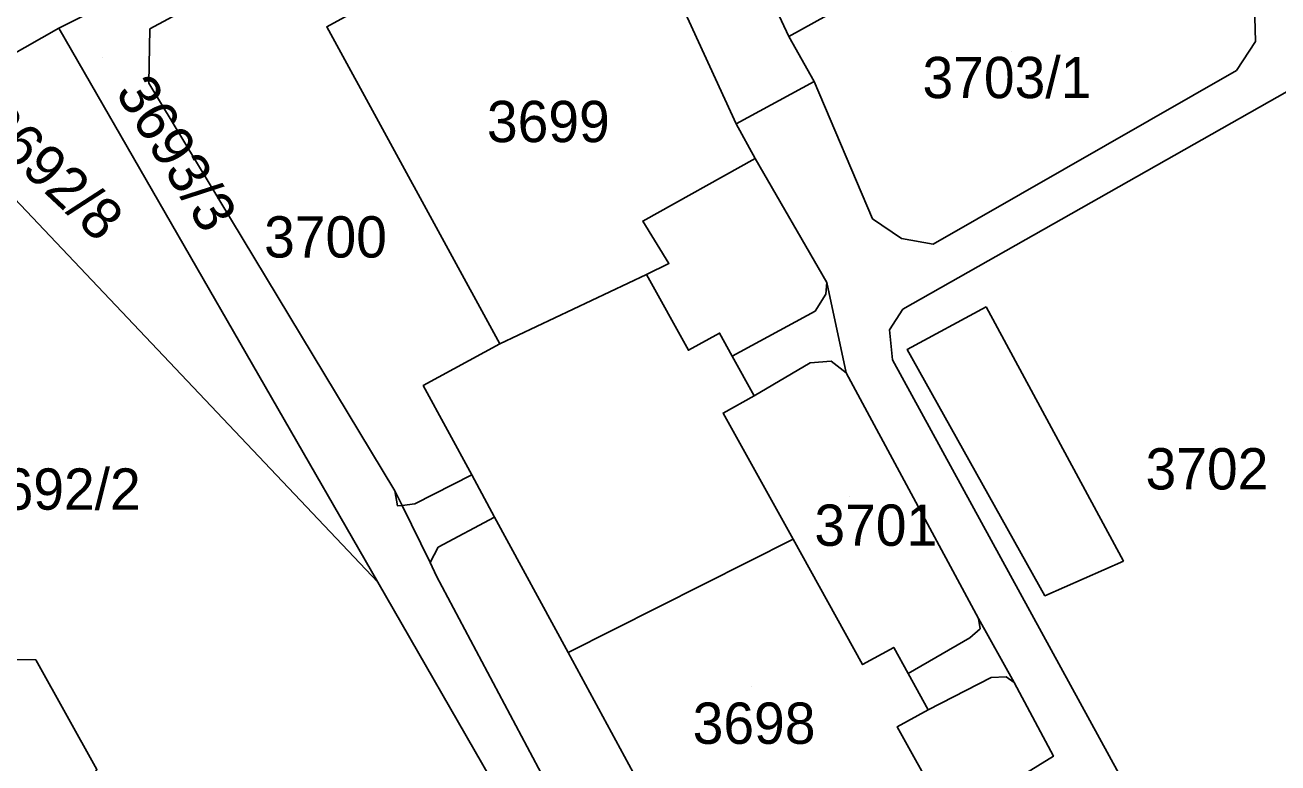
# Model space of a CAD drawing. Extents: x -262715 to -259381, y -1237238 to -1231182.
# Drawn here: x -261788.7 to -261728, y -1235674.8 to -1235639 of the extents above; entities that cross this region are included whole.
import ezdxf

# ---------------------------------------------------------------- set-up
doc = ezdxf.new("R2010")
doc.units = 0
for name, color, linetype in [('body_kn', 7, 'Continuous'), ('kladpar_druhypozemkov', 7, 'Continuous'), ('kladpar_hranice', 7, 'Continuous'), ('kladpar_parcelnecisla', 7, 'Continuous'), ('kladpar_plochy', 7, 'Continuous'), ('zappar_hrandruhpozemk', 7, 'Continuous')]:
    doc.layers.add(name, color=color, linetype=linetype)

msp = doc.modelspace()

# ---------------------------------------------------------------- linework, layer by layer
at = {"layer": 'body_kn'}
for p, q in [((-261787.06, -1235639.18), (-261787.06, -1235639.18)), ((-261787.06, -1235639.18), (-261787.06, -1235639.18)), ((-261782.66, -1235639.22), (-261782.66, -1235639.22)), ((-261774.08, -1235639.11), (-261774.08, -1235639.11)), ((-261751.7, -1235639.59), (-261751.7, -1235639.59)), ((-261729.08, -1235639.83), (-261729.08, -1235639.83)), ((-261730, -1235641.23), (-261730, -1235641.23)), ((-261782.71, -1235641.84), (-261782.71, -1235641.84)), ((-261750.47, -1235641.76), (-261750.47, -1235641.76)), ((-261754.24, -1235643.82), (-261754.24, -1235643.82)), ((-261753.32, -1235645.49), (-261753.32, -1235645.49)), ((-261753.32, -1235645.49), (-261753.32, -1235645.49)), ((-261758.77, -1235648.52), (-261758.77, -1235648.52)), ((-261747.64, -1235648.41), (-261747.64, -1235648.41)), ((-261746.24, -1235649.37), (-261746.24, -1235649.37)), ((-261744.7, -1235649.64), (-261744.7, -1235649.64)), ((-261757.51, -1235650.57), (-261757.51, -1235650.57)), ((-261758.6, -1235651.11), (-261758.6, -1235651.11)), ((-261758.6, -1235651.11), (-261758.6, -1235651.11)), ((-261749.85, -1235651.5), (-261749.85, -1235651.5)), ((-261749.85, -1235651.5), (-261749.85, -1235651.5)), ((-261749.91, -1235652.06), (-261749.91, -1235652.06)), ((-261750.42, -1235652.89), (-261750.42, -1235652.89)), ((-261746.17, -1235652.79), (-261746.17, -1235652.79)), ((-261742.14, -1235652.68), (-261742.14, -1235652.68)), ((-261742.14, -1235652.68), (-261742.14, -1235652.68)), ((-261755.05, -1235653.95), (-261755.05, -1235653.95)), ((-261746.82, -1235653.79), (-261746.82, -1235653.79)), ((-261765.69, -1235654.47), (-261765.69, -1235654.47)), ((-261756.56, -1235654.78), (-261756.56, -1235654.78)), ((-261754.44, -1235655.06), (-261754.44, -1235655.06)), ((-261749.65, -1235655.3), (-261749.65, -1235655.3)), ((-261746.67, -1235655.25), (-261746.67, -1235655.25)), ((-261745.96, -1235654.74), (-261745.96, -1235654.74)), ((-261750.67, -1235655.39), (-261750.67, -1235655.39)), ((-261748.92, -1235655.88), (-261748.92, -1235655.88)), ((-261769.41, -1235656.49), (-261769.41, -1235656.49)), ((-261753.37, -1235656.99), (-261753.37, -1235656.99)), ((-261753.37, -1235656.99), (-261753.37, -1235656.99)), ((-261754.88, -1235657.82), (-261754.88, -1235657.82)), ((-261767.05, -1235660.82), (-261767.05, -1235660.82)), ((-261767.05, -1235660.82), (-261767.05, -1235660.82)), ((-261770.78, -1235661.58), (-261770.78, -1235661.58)), ((-261770.65, -1235662.32), (-261770.65, -1235662.32)), ((-261770.43, -1235662.29), (-261770.43, -1235662.29)), ((-261770.43, -1235662.29), (-261770.43, -1235662.29)), ((-261769.81, -1235662.22), (-261769.81, -1235662.22)), ((-261765.95, -1235662.86), (-261765.95, -1235662.86)), ((-261765.95, -1235662.86), (-261765.95, -1235662.86)), ((-261768.68, -1235664.32), (-261768.68, -1235664.32)), ((-261751.49, -1235663.92), (-261751.49, -1235663.92)), ((-261751.49, -1235663.92), (-261751.49, -1235663.92)), ((-261735.48, -1235665), (-261735.48, -1235665)), ((-261769.08, -1235665.05), (-261769.08, -1235665.05)), ((-261771.61, -1235666.01), (-261771.61, -1235666.01)), ((-261771.61, -1235666.01), (-261771.61, -1235666.01)), ((-261768.76, -1235665.72), (-261768.76, -1235665.72)), ((-261739.29, -1235666.67), (-261739.29, -1235666.67)), ((-261742.51, -1235667.77), (-261742.51, -1235667.77)), ((-261742.51, -1235667.77), (-261742.51, -1235667.77)), ((-261742.42, -1235668.27), (-261742.42, -1235668.27)), ((-261746.61, -1235669.17), (-261746.61, -1235669.17)), ((-261742.93, -1235668.7), (-261742.93, -1235668.7)), ((-261788.18, -1235669.77), (-261788.18, -1235669.77)), ((-261762.39, -1235669.41), (-261762.39, -1235669.41)), ((-261748.12, -1235670), (-261748.12, -1235670)), ((-261745.91, -1235670.44), (-261745.91, -1235670.44)), ((-261741.9, -1235670.62), (-261741.9, -1235670.62)), ((-261741.17, -1235670.59), (-261741.17, -1235670.59)), ((-261740.78, -1235670.87), (-261740.78, -1235670.87)), ((-261744.94, -1235672.19), (-261744.94, -1235672.19)), ((-261744.94, -1235672.19), (-261744.94, -1235672.19)), ((-261746.45, -1235673.02), (-261746.45, -1235673.02)), ((-261738.88, -1235674.44), (-261738.88, -1235674.44))]:
    msp.add_line(p, q, dxfattribs=at)
at = {"layer": 'kladpar_druhypozemkov'}
for p, q in [((-261784.94, -1235640.58), (-261784.94, -1235640.58)), ((-261740.91, -1235640.29), (-261740.91, -1235640.29)), ((-261763.21, -1235642.76), (-261763.21, -1235642.76)), ((-261786.49, -1235645.69), (-261786.49, -1235645.69)), ((-261774.4, -1235648.58), (-261774.4, -1235648.58)), ((-261731.03, -1235659.45), (-261731.03, -1235659.45)), ((-261786.19, -1235660.91), (-261786.19, -1235660.91)), ((-261748.77, -1235661.87), (-261748.77, -1235661.87)), ((-261753.52, -1235671.05), (-261753.52, -1235671.05))]:
    msp.add_line(p, q, dxfattribs=at)
at = {"layer": 'kladpar_hranice'}
for points in [[(-261746.87, -1235614.31), (-261744.89, -1235617.96), (-261743.11, -1235621.2), (-261744.08, -1235621.73), (-261743.02, -1235623.67), (-261740.4, -1235622.23), (-261735.74, -1235630.75), (-261751.7, -1235639.59), (-261755.64, -1235631.15), (-261753.61, -1235629.87), (-261756.52, -1235624.52), (-261755.14, -1235623.41), (-261755.48, -1235622.77), (-261756.99, -1235619.94), (-261746.87, -1235614.31)], [(-261741.48, -1235615.82), (-261739.49, -1235619.29), (-261738.43, -1235621.27), (-261729.14, -1235638.06), (-261729.08, -1235639.83), (-261730, -1235641.23), (-261744.7, -1235649.64), (-261746.24, -1235649.37), (-261747.64, -1235648.41), (-261750.47, -1235641.76), (-261751.7, -1235639.59), (-261735.74, -1235630.75), (-261740.4, -1235622.23), (-261743.02, -1235623.67), (-261744.08, -1235621.73), (-261743.11, -1235621.2), (-261744.89, -1235617.96), (-261741.48, -1235615.82)], [(-261787.06, -1235639.18), (-261782.81, -1235637.04), (-261775.1, -1235633.15), (-261772.73, -1235630.76), (-261772.47, -1235630.53)], [(-261755.64, -1235631.15), (-261751.7, -1235639.59), (-261750.47, -1235641.76), (-261754.24, -1235643.82), (-261753.32, -1235645.49), (-261758.77, -1235648.52), (-261757.51, -1235650.57), (-261758.6, -1235651.11), (-261765.69, -1235654.47), (-261774.08, -1235639.11), (-261765.58, -1235634.46), (-261764.15, -1235636.92), (-261762.21, -1235635.85), (-261762.74, -1235634.88), (-261759.23, -1235632.96), (-261755.64, -1235631.15)], [(-261793.56, -1235642.86), (-261798.21, -1235637.96), (-261797.99, -1235637.92), (-261787.61, -1235632), (-261782.81, -1235637.04), (-261787.06, -1235639.18), (-261793.56, -1235642.86)], [(-261762.72, -1235677.09), (-261768.76, -1235665.72), (-261769.08, -1235665.05), (-261770.43, -1235662.29), (-261770.78, -1235661.58), (-261782.71, -1235641.84), (-261782.66, -1235639.22), (-261770.45, -1235632.64)], [(-261770.45, -1235632.64), (-261782.66, -1235639.22), (-261782.71, -1235641.84), (-261770.78, -1235661.58), (-261770.43, -1235662.29), (-261769.08, -1235665.05), (-261768.76, -1235665.72), (-261762.72, -1235677.09)], [(-261765.58, -1235634.46), (-261774.08, -1235639.11), (-261765.69, -1235654.47), (-261769.41, -1235656.49), (-261767.05, -1235660.82), (-261765.95, -1235662.86), (-261762.39, -1235669.41), (-261758.82, -1235676)], [(-261726.07, -1235688.93), (-261728.83, -1235696.49), (-261728.34, -1235694.86), (-261728.71, -1235693), (-261733.78, -1235683.75), (-261735.92, -1235679.87), (-261737.19, -1235677.55), (-261742.41, -1235680.43), (-261743.98, -1235677.59), (-261738.88, -1235674.44), (-261740.78, -1235670.87), (-261742.51, -1235667.77), (-261748.92, -1235655.88), (-261749.85, -1235651.5), (-261753.32, -1235645.49), (-261754.24, -1235643.82), (-261750.47, -1235641.76), (-261747.64, -1235648.41), (-261746.24, -1235649.37), (-261744.7, -1235649.64), (-261730, -1235641.23), (-261729.08, -1235639.83), (-261729.14, -1235638.06)], [(-261771.61, -1235666.01), (-261793.56, -1235642.86), (-261787.06, -1235639.18), (-261771.61, -1235666.01)], [(-261765.78, -1235676.15), (-261771.61, -1235666.01), (-261787.06, -1235639.18)], [(-261721.34, -1235645.46), (-261721.45, -1235663.19), (-261721.77, -1235676.13), (-261721.89, -1235682.46), (-261724.87, -1235687.88), (-261726.07, -1235688.93), (-261727.44, -1235689.02), (-261728.49, -1235688.46), (-261746.67, -1235655.25), (-261746.82, -1235653.79), (-261746.17, -1235652.79), (-261725.73, -1235641.21), (-261724.22, -1235640.89), (-261722.8, -1235641.31), (-261721.25, -1235642.86), (-261721.34, -1235645.46)], [(-261725.73, -1235641.21), (-261746.17, -1235652.79), (-261746.82, -1235653.79), (-261746.67, -1235655.25), (-261728.49, -1235688.46), (-261727.44, -1235689.02)], [(-261793.56, -1235642.86), (-261771.61, -1235666.01), (-261765.78, -1235676.15), (-261780.48, -1235684.16), (-261783.34, -1235684.15), (-261785.63, -1235682.73), (-261786.89, -1235680.9), (-261786.92, -1235678.28), (-261785.22, -1235675.09), (-261788.18, -1235669.77), (-261790.97, -1235669.73), (-261793.34, -1235668.35), (-261794.56, -1235666.02), (-261794.55, -1235663.58), (-261792.74, -1235660.97), (-261795.77, -1235655.64), (-261797.7, -1235656.01), (-261800, -1235655.29), (-261801.67, -1235653.66), (-261802.55, -1235651.24), (-261802.11, -1235648.87), (-261800.44, -1235646.76), (-261793.56, -1235642.86)], [(-261753.32, -1235645.49), (-261749.85, -1235651.5), (-261748.92, -1235655.88), (-261742.51, -1235667.77), (-261740.78, -1235670.87), (-261738.88, -1235674.44), (-261743.98, -1235677.59), (-261744.45, -1235676.62), (-261746.45, -1235673.02), (-261744.94, -1235672.19), (-261745.91, -1235670.44), (-261746.61, -1235669.17), (-261748.12, -1235670), (-261751.49, -1235663.92), (-261754.88, -1235657.82), (-261753.37, -1235656.99), (-261754.44, -1235655.06), (-261755.05, -1235653.95), (-261756.56, -1235654.78), (-261758.6, -1235651.11), (-261757.51, -1235650.57), (-261758.77, -1235648.52), (-261753.32, -1235645.49)], [(-261790.97, -1235669.73), (-261788.18, -1235669.77), (-261785.22, -1235675.09), (-261786.92, -1235678.28), (-261786.89, -1235680.9), (-261785.63, -1235682.73), (-261783.34, -1235684.15), (-261780.48, -1235684.16), (-261765.78, -1235676.15), (-261761.54, -1235683.52), (-261785.68, -1235696.18), (-261809.78, -1235651.59)], [(-261758.6, -1235651.11), (-261756.56, -1235654.78), (-261755.05, -1235653.95), (-261754.44, -1235655.06), (-261753.37, -1235656.99), (-261754.88, -1235657.82), (-261751.49, -1235663.92), (-261748.12, -1235670), (-261746.61, -1235669.17), (-261745.91, -1235670.44), (-261744.94, -1235672.19), (-261746.45, -1235673.02), (-261744.45, -1235676.62), (-261754.91, -1235682.08), (-261755.38, -1235682.34), (-261757.72, -1235678.03), (-261758.82, -1235676), (-261762.39, -1235669.41), (-261765.95, -1235662.86), (-261767.05, -1235660.82), (-261769.41, -1235656.49), (-261765.69, -1235654.47), (-261758.6, -1235651.11)]]:
    msp.add_lwpolyline(points, dxfattribs=at)
at = {"layer": 'kladpar_plochy'}
for points in [[(-261746.87, -1235614.31), (-261744.89, -1235617.96), (-261743.11, -1235621.2), (-261744.08, -1235621.73), (-261743.02, -1235623.67), (-261740.4, -1235622.23), (-261735.74, -1235630.75), (-261751.7, -1235639.59), (-261755.64, -1235631.15), (-261753.61, -1235629.87), (-261756.52, -1235624.52), (-261755.14, -1235623.41), (-261755.48, -1235622.77), (-261756.99, -1235619.94)], [(-261741.48, -1235615.82), (-261739.49, -1235619.29), (-261738.43, -1235621.27), (-261729.14, -1235638.06), (-261729.08, -1235639.83), (-261730, -1235641.23), (-261744.7, -1235649.64), (-261746.24, -1235649.37), (-261747.64, -1235648.41), (-261750.47, -1235641.76), (-261751.7, -1235639.59), (-261735.74, -1235630.75), (-261740.4, -1235622.23), (-261743.02, -1235623.67), (-261744.08, -1235621.73), (-261743.11, -1235621.2), (-261744.89, -1235617.96)], [(-261755.64, -1235631.15), (-261751.7, -1235639.59), (-261750.47, -1235641.76), (-261754.24, -1235643.82), (-261753.32, -1235645.49), (-261758.77, -1235648.52), (-261757.51, -1235650.57), (-261758.6, -1235651.11), (-261765.69, -1235654.47), (-261774.08, -1235639.11), (-261765.58, -1235634.46), (-261764.15, -1235636.92), (-261762.21, -1235635.85), (-261762.74, -1235634.88), (-261759.23, -1235632.96)], [(-261793.56, -1235642.86), (-261798.21, -1235637.96), (-261797.99, -1235637.92), (-261787.61, -1235632), (-261782.81, -1235637.04), (-261787.06, -1235639.18)], [(-261771.61, -1235666.01), (-261793.56, -1235642.86), (-261787.06, -1235639.18)], [(-261721.34, -1235645.46), (-261721.45, -1235663.19), (-261721.77, -1235676.13), (-261721.89, -1235682.46), (-261724.87, -1235687.88), (-261726.07, -1235688.93), (-261727.44, -1235689.02), (-261728.49, -1235688.46), (-261746.67, -1235655.25), (-261746.82, -1235653.79), (-261746.17, -1235652.79), (-261725.73, -1235641.21), (-261724.22, -1235640.89), (-261722.8, -1235641.31), (-261721.25, -1235642.86)], [(-261793.56, -1235642.86), (-261771.61, -1235666.01), (-261765.78, -1235676.15), (-261780.48, -1235684.16), (-261783.34, -1235684.15), (-261785.63, -1235682.73), (-261786.89, -1235680.9), (-261786.92, -1235678.28), (-261785.22, -1235675.09), (-261788.18, -1235669.77), (-261790.97, -1235669.73), (-261793.34, -1235668.35), (-261794.56, -1235666.02), (-261794.55, -1235663.58), (-261792.74, -1235660.97), (-261795.77, -1235655.64), (-261797.7, -1235656.01), (-261800, -1235655.29), (-261801.67, -1235653.66), (-261802.55, -1235651.24), (-261802.11, -1235648.87), (-261800.44, -1235646.76)], [(-261753.32, -1235645.49), (-261749.85, -1235651.5), (-261748.92, -1235655.88), (-261742.51, -1235667.77), (-261740.78, -1235670.87), (-261738.88, -1235674.44), (-261743.98, -1235677.59), (-261744.45, -1235676.62), (-261746.45, -1235673.02), (-261744.94, -1235672.19), (-261745.91, -1235670.44), (-261746.61, -1235669.17), (-261748.12, -1235670), (-261751.49, -1235663.92), (-261754.88, -1235657.82), (-261753.37, -1235656.99), (-261754.44, -1235655.06), (-261755.05, -1235653.95), (-261756.56, -1235654.78), (-261758.6, -1235651.11), (-261757.51, -1235650.57), (-261758.77, -1235648.52)], [(-261758.6, -1235651.11), (-261756.56, -1235654.78), (-261755.05, -1235653.95), (-261754.44, -1235655.06), (-261753.37, -1235656.99), (-261754.88, -1235657.82), (-261751.49, -1235663.92), (-261748.12, -1235670), (-261746.61, -1235669.17), (-261745.91, -1235670.44), (-261744.94, -1235672.19), (-261746.45, -1235673.02), (-261744.45, -1235676.62), (-261754.91, -1235682.08), (-261755.38, -1235682.34), (-261757.72, -1235678.03), (-261758.82, -1235676), (-261762.39, -1235669.41), (-261765.95, -1235662.86), (-261767.05, -1235660.82), (-261769.41, -1235656.49), (-261765.69, -1235654.47)]]:
    msp.add_lwpolyline(points, close=True, dxfattribs=at)
for points in [[(-261762.72, -1235677.09), (-261768.76, -1235665.72), (-261769.08, -1235665.05), (-261770.43, -1235662.29), (-261770.78, -1235661.58), (-261782.71, -1235641.84), (-261782.66, -1235639.22), (-261770.45, -1235632.64)], [(-261770.45, -1235632.64), (-261782.66, -1235639.22), (-261782.71, -1235641.84), (-261770.78, -1235661.58), (-261770.43, -1235662.29), (-261769.08, -1235665.05), (-261768.76, -1235665.72), (-261762.72, -1235677.09)], [(-261765.58, -1235634.46), (-261774.08, -1235639.11), (-261765.69, -1235654.47), (-261769.41, -1235656.49), (-261767.05, -1235660.82), (-261765.95, -1235662.86), (-261762.39, -1235669.41), (-261758.82, -1235676)], [(-261765.78, -1235676.15), (-261771.61, -1235666.01), (-261787.06, -1235639.18), (-261782.81, -1235637.04)], [(-261726.07, -1235688.93), (-261728.83, -1235696.49), (-261728.34, -1235694.86), (-261728.71, -1235693), (-261733.78, -1235683.75), (-261735.92, -1235679.87), (-261737.19, -1235677.55), (-261742.41, -1235680.43), (-261743.98, -1235677.59), (-261738.88, -1235674.44), (-261740.78, -1235670.87), (-261742.51, -1235667.77), (-261748.92, -1235655.88), (-261749.85, -1235651.5), (-261753.32, -1235645.49), (-261754.24, -1235643.82), (-261750.47, -1235641.76), (-261747.64, -1235648.41), (-261746.24, -1235649.37), (-261744.7, -1235649.64), (-261730, -1235641.23), (-261729.08, -1235639.83), (-261729.14, -1235638.06)], [(-261725.73, -1235641.21), (-261746.17, -1235652.79), (-261746.82, -1235653.79), (-261746.67, -1235655.25), (-261728.49, -1235688.46), (-261727.44, -1235689.02)], [(-261790.97, -1235669.73), (-261788.18, -1235669.77), (-261785.22, -1235675.09), (-261786.92, -1235678.28), (-261786.89, -1235680.9), (-261785.63, -1235682.73), (-261783.34, -1235684.15), (-261780.48, -1235684.16), (-261765.78, -1235676.15), (-261761.54, -1235683.52), (-261785.68, -1235696.18), (-261809.78, -1235651.59)]]:
    msp.add_lwpolyline(points, dxfattribs=at)
at = {"layer": 'zappar_hrandruhpozemk'}
for p, q in [((-261759.23, -1235632.96), (-261754.24, -1235643.82)), ((-261750.42, -1235652.89), (-261754.44, -1235655.06)), ((-261742.14, -1235652.68), (-261735.48, -1235665)), ((-261753.37, -1235656.99), (-261750.67, -1235655.39)), ((-261767.05, -1235660.82), (-261769.81, -1235662.22)), ((-261769.81, -1235662.22), (-261770.43, -1235662.29)), ((-261765.95, -1235662.86), (-261768.68, -1235664.32)), ((-261751.49, -1235663.92), (-261762.39, -1235669.41)), ((-261742.93, -1235668.7), (-261745.91, -1235670.44)), ((-261744.94, -1235672.19), (-261741.9, -1235670.62))]:
    msp.add_line(p, q, dxfattribs=at)
for points in [[(-261749.85, -1235651.5), (-261749.91, -1235652.06), (-261750.42, -1235652.89)], [(-261735.48, -1235665), (-261739.29, -1235666.67), (-261745.96, -1235654.74), (-261742.14, -1235652.68)], [(-261750.67, -1235655.39), (-261749.65, -1235655.3), (-261748.92, -1235655.88)], [(-261770.43, -1235662.29), (-261770.65, -1235662.32), (-261770.78, -1235661.58)], [(-261768.68, -1235664.32), (-261769.08, -1235665.05), (-261768.76, -1235665.72)], [(-261742.51, -1235667.77), (-261742.42, -1235668.27), (-261742.93, -1235668.7)], [(-261741.9, -1235670.62), (-261741.17, -1235670.59), (-261740.78, -1235670.87)]]:
    msp.add_lwpolyline(points, dxfattribs=at)

# ---------------------------------------------------------------- texts
at = {"layer": 'kladpar_parcelnecisla'}
for s, p in [('3703/1', (-261745.22, -1235642.57)), ('3699', (-261766.322, -1235644.7)), ('3700', (-261777.118, -1235650.29)), ('3702', (-261734.413, -1235661.52)), ('3692/2', (-261791.276, -1235662.5)), ('3701', (-261750.457, -1235664.25)), ('3698', (-261756.356, -1235673.84))]:
    msp.add_text(s, height=2, dxfattribs=at).set_placement(p)
for s, rotation, p in [('3693/3', 302, (-261784.361, -1235642.286)), ('3692/8', 317, (-261791.115, -1235644.039))]:
    msp.add_text(s, height=2, rotation=rotation, dxfattribs=at).set_placement(p)

doc.saveas('drawing.dxf')
